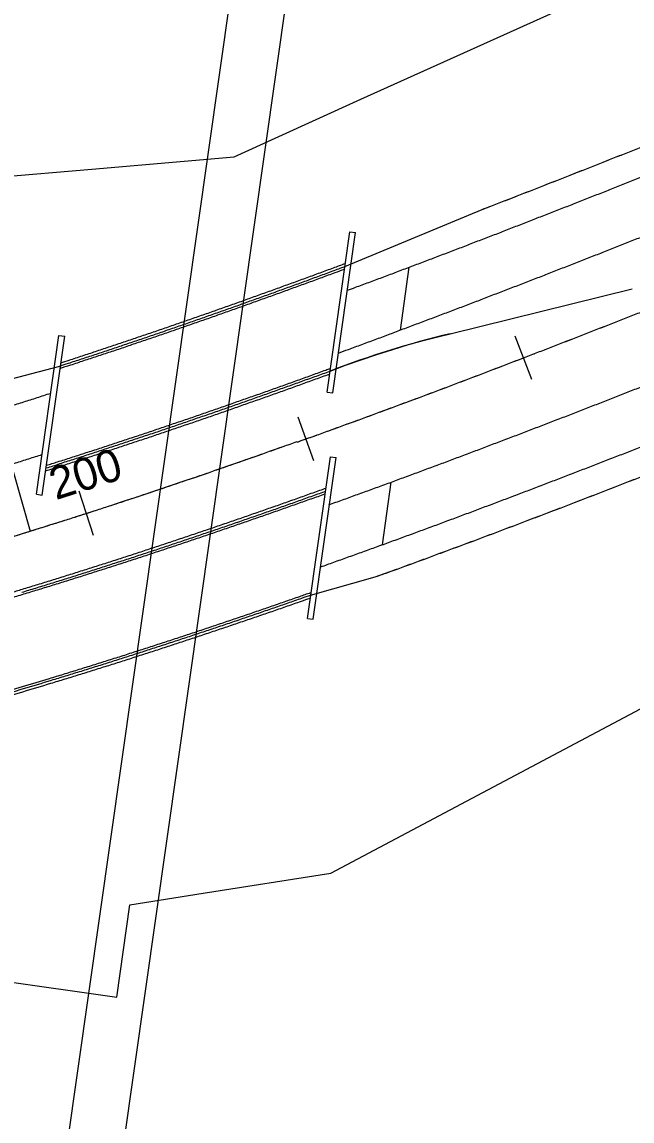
# Model space of a CAD drawing. Extents: x 0 to 3400, y 0 to 2200.
# Drawn here: x 2021.7 to 2284.4, y 258 to 731 of the extents above; entities that cross this region are included whole.
import ezdxf

# ---------------------------------------------------------------- set-up
doc = ezdxf.new("R2010")
doc.units = 0
for name, color, linetype in [('Default', 7, 'Continuous'), ('GE_P_CL_100', 7, 'Continuous'), ('PV_P_EOP', 7, 'Continuous'), ('PV_X_EOP', 7, 'Continuous'), ('RD_X_GR_Lt', 7, 'Continuous'), ('RD_X_GR_Rt', 7, 'Continuous'), ('RW_X_Esmt_LA', 7, 'Continuous'), ('SC_Scratch10', 7, 'Continuous'), ('SH_Data', 7, 'Continuous')]:
    doc.layers.add(name, color=color, linetype=linetype)

msp = doc.modelspace()

# ---------------------------------------------------------------- linework, layer by layer
at = {"layer": 'Default'}
for p, q in [((2160.68, 625.76), (2219.83, 650.31)), ((2160.68, 625.76), (2219.83, 650.31)), ((2153.09, 571.76), (2162.92, 640.75)), ((2155.56, 571.41), (2165.39, 640.4)), ((2162.92, 640.75), (2165.39, 640.4)), ((2184.67, 598.42), (2188.52, 625.5)), ((2206.08, 596.85), (2284.41, 616.22)), ((2206.08, 596.85), (2284.41, 616.22)), ((2027.91, 527.76), (2037.65, 596.09)), ((2037.65, 596.09), (2040.12, 595.74)), ((2030.39, 527.41), (2040.12, 595.74)), ((2241.28, 577.13), (2234.1, 595.79)), ((2153.09, 571.76), (2155.56, 571.41)), ((2147.35, 542.14), (2140.6, 560.97)), ((2144.61, 474.3), (2154.52, 543.85)), ((2147.08, 473.94), (2156.99, 543.5)), ((2154.52, 543.85), (2156.99, 543.5)), ((2176.91, 506.02), (2180.75, 532.97)), ((2027.91, 527.76), (2030.39, 527.41)), ((2052.51, 510), (2046.37, 529.03)), ((2146, 484.38), (2173.87, 492.17)), ((2146, 484.38), (2173.87, 492.17)), ((2144.61, 474.3), (2147.08, 473.94))]:
    msp.add_line(p, q, dxfattribs=at)
for points in [[(2247.02, 590.06), (2247.49, 590.24), (2250.36, 591.35), (2253.23, 592.46), (2256.09, 593.58), (2258.96, 594.69), (2261.83, 595.81), (2264.69, 596.93), (2267.56, 598.05), (2270.42, 599.17), (2273.29, 600.29), (2276.16, 601.41), (2279.02, 602.54), (2281.88, 603.66), (2284.75, 604.79)], [(2237.69, 586.46), (2238.87, 586.91), (2241.74, 588.02), (2242.36, 588.26)], [(2153.39, 554.94), (2155.3, 555.63), (2158.2, 556.68), (2161.09, 557.73), (2163.98, 558.79), (2166.87, 559.84), (2169.76, 560.9), (2172.65, 561.96), (2175.54, 563.02), (2178.42, 564.09), (2181.31, 565.16), (2184.19, 566.23), (2187.08, 567.3), (2189.96, 568.37), (2192.84, 569.45), (2195.73, 570.53), (2198.61, 571.6), (2201.49, 572.69), (2204.37, 573.77), (2207.25, 574.85), (2210.13, 575.94), (2213, 577.03), (2215.88, 578.12), (2218.76, 579.21), (2221.63, 580.31), (2224.51, 581.41), (2227.38, 582.51), (2228.35, 582.88)], [(2233.02, 584.67), (2233.13, 584.71), (2236, 585.81), (2237.69, 586.46)], [(2139.36, 550.15), (2140.05, 550.4), (2140.08, 550.41), (2140.1, 550.42), (2140.24, 550.22), (2141.98, 550.84), (2143.72, 551.46), (2143.98, 551.55)], [(2143.98, 551.55), (2146.62, 552.5), (2148.68, 553.24)], [(2058.95, 522.6), (2060.82, 523.21), (2063.77, 524.17), (2066.72, 525.14), (2069.67, 526.12), (2072.62, 527.1), (2075.56, 528.08), (2078.51, 529.06), (2081.45, 530.05), (2084.39, 531.04), (2087.34, 532.03), (2090.28, 533.03), (2093.22, 534.03), (2096.15, 535.03), (2099.09, 536.03), (2102.02, 537.04), (2104.95, 538.05), (2107.89, 539.07), (2110.82, 540.08), (2113.75, 541.1), (2116.67, 542.13), (2119.6, 543.15), (2122.53, 544.18), (2125.45, 545.21), (2128.37, 546.24), (2131.3, 547.28), (2134.22, 548.32), (2134.65, 548.47)], [(2049.44, 519.51), (2051.96, 520.33), (2054.2, 521.05)], [(1963.23, 493.66), (1979.89, 498.3), (2004.37, 505.47), (2010.43, 507.31), (2013.41, 508.21), (2016.38, 509.12), (2019.35, 510.03), (2022.32, 510.95), (2025.29, 511.87), (2028.26, 512.8), (2031.23, 513.72), (2034.19, 514.66), (2037.16, 515.59), (2039.91, 516.47)], [(2044.68, 517.98), (2046.04, 518.42), (2049, 519.37), (2049.44, 519.51)]]:
    msp.add_lwpolyline(points, dxfattribs=at)
for centre, radius, start, end in [((2301.32, 199.25), 408.84, 103.4712, 111.0638), ((2301.32, 199.25), 408.84, 103.4712, 111.0638), ((1349.37, 2701.71), 2316.83, 286.73456, 286.891), ((1349.37, 2701.71), 2314.66, 286.75999, 286.891), ((1349.37, 2701.71), 2357, 286.27879, 286.891), ((1349.95, 2701.92), 2355.83, 286.27879, 286.891), ((1349.37, 2701.71), 2354.83, 286.3024, 286.891)]:
    msp.add_arc(centre, radius, start, end, dxfattribs=at)
for points in [[(2219.83, 650.31), (2223.67, 651.79), (2229.34, 653.99), (2235.02, 656.2), (2240.7, 658.41), (2246.38, 660.63), (2252.06, 662.85), (2257.73, 665.08), (2263.41, 667.32), (2269.09, 669.56), (2274.78, 671.81), (2280.46, 674.06), (2286.14, 676.31), (2291.82, 678.57), (2297.51, 680.83), (2303.2, 683.1), (2306.07, 684.25)], [(2219.83, 650.31), (2223.67, 651.79), (2229.34, 653.99), (2235.02, 656.2), (2240.7, 658.41), (2246.38, 660.63), (2252.06, 662.85), (2257.73, 665.08), (2263.41, 667.32), (2269.09, 669.56), (2274.78, 671.81), (2280.46, 674.06), (2286.14, 676.31), (2291.82, 678.57), (2297.51, 680.83), (2303.2, 683.1), (2306.07, 684.25)], [(2140.24, 550.22), (2143.72, 551.46), (2149.52, 553.54), (2155.3, 555.63), (2161.09, 557.73), (2166.87, 559.84), (2172.65, 561.96), (2178.42, 564.09), (2184.19, 566.23), (2189.96, 568.37), (2195.73, 570.53), (2201.49, 572.69), (2207.25, 574.85), (2213, 577.03), (2218.76, 579.21), (2224.51, 581.41), (2230.26, 583.61), (2236, 585.81), (2241.74, 588.02), (2247.49, 590.24), (2253.23, 592.46), (2258.96, 594.69), (2264.69, 596.93), (2270.42, 599.17), (2276.16, 601.41), (2281.88, 603.66), (2287.61, 605.91), (2293.33, 608.17), (2299.06, 610.43), (2304.78, 612.7), (2310.5, 614.97), (2316.22, 617.24), (2321.93, 619.52), (2327.65, 621.8), (2333.36, 624.08), (2339.08, 626.36), (2344.79, 628.65), (2350.51, 630.94), (2356.22, 633.23), (2361.93, 635.52), (2367.64, 637.81), (2373.36, 640.1), (2379.07, 642.4), (2384.77, 644.69), (2390.49, 646.99)], [(2038.01, 581.92), (2042.71, 583.44), (2048.42, 585.31), (2054.13, 587.19), (2059.83, 589.08), (2065.53, 590.99), (2071.24, 592.92), (2076.93, 594.85), (2082.63, 596.8), (2088.33, 598.76), (2094.03, 600.73), (2099.72, 602.72), (2105.42, 604.72), (2111.11, 606.72), (2116.79, 608.74), (2122.48, 610.78), (2128.17, 612.82), (2133.86, 614.87), (2139.54, 616.94), (2145.23, 619.01), (2150.92, 621.1), (2156.6, 623.19), (2160.54, 624.65)], [(2038.07, 582.95), (2041.69, 584.13), (2047.4, 585.99), (2053.1, 587.87), (2058.81, 589.77), (2064.51, 591.68), (2070.21, 593.6), (2075.9, 595.53), (2081.6, 597.48), (2087.3, 599.44), (2092.99, 601.41), (2098.68, 603.4), (2104.38, 605.39), (2110.06, 607.4), (2115.75, 609.42), (2121.44, 611.45), (2127.13, 613.49), (2132.81, 615.55), (2138.5, 617.61), (2144.18, 619.68), (2149.86, 621.77), (2155.54, 623.86), (2160.68, 625.76)], [(2038.42, 584.33), (2042.04, 585.5), (2047.74, 587.37), (2053.45, 589.25), (2059.15, 591.14), (2064.84, 593.05), (2070.54, 594.97), (2076.23, 596.9), (2081.93, 598.85), (2087.62, 600.81), (2093.32, 602.78), (2099.01, 604.77), (2104.7, 606.76), (2110.38, 608.77), (2116.07, 610.78), (2121.75, 612.82), (2127.44, 614.86), (2133.12, 616.91), (2138.8, 618.97), (2144.49, 621.05), (2150.17, 623.13), (2155.85, 625.22), (2160.99, 627.12)], [(2032.19, 540.17), (2037.08, 541.71), (2042.88, 543.56), (2048.68, 545.43), (2054.48, 547.31), (2060.27, 549.21), (2066.06, 551.11), (2071.85, 553.04), (2077.63, 554.97), (2083.41, 556.92), (2089.19, 558.88), (2094.96, 560.86), (2100.73, 562.84), (2106.5, 564.84), (2112.27, 566.85), (2118.03, 568.87), (2123.79, 570.9), (2129.54, 572.95), (2135.3, 575), (2141.05, 577.07), (2146.8, 579.14), (2152.54, 581.23), (2154.5, 581.94)], [(2173.87, 492.17), (2177.77, 493.57), (2183.66, 495.71), (2189.54, 497.86), (2195.42, 500.01), (2201.29, 502.18), (2207.15, 504.35), (2213.01, 506.53), (2218.86, 508.71), (2224.71, 510.91), (2230.55, 513.11), (2236.39, 515.31), (2242.22, 517.53), (2248.05, 519.75), (2253.87, 521.97), (2259.68, 524.21), (2265.49, 526.44), (2271.3, 528.69), (2277.1, 530.93), (2282.9, 533.19), (2288.68, 535.44), (2294.47, 537.7), (2300.25, 539.97), (2306.03, 542.24), (2311.81, 544.51), (2317.57, 546.79), (2323.34, 549.06), (2329.1, 551.35), (2334.86, 553.63), (2340.61, 555.92), (2346.36, 558.2), (2352.11, 560.5), (2357.85, 562.79), (2363.58, 565.08), (2369.32, 567.38), (2375.05, 569.67), (2380.78, 571.97), (2386.51, 574.26), (2392.23, 576.56), (2397.95, 578.86), (2403.67, 581.15), (2409.38, 583.45), (2415.09, 585.74)], [(2173.87, 492.17), (2177.77, 493.57), (2183.66, 495.71), (2189.54, 497.86), (2195.42, 500.01), (2201.29, 502.18), (2207.15, 504.35), (2213.01, 506.53), (2218.86, 508.71), (2224.71, 510.91), (2230.55, 513.11), (2236.39, 515.31), (2242.22, 517.53), (2248.05, 519.75), (2253.87, 521.97), (2259.68, 524.21), (2265.49, 526.44), (2271.3, 528.69), (2277.1, 530.93), (2282.9, 533.19), (2288.68, 535.44), (2294.47, 537.7), (2300.25, 539.97), (2306.03, 542.24), (2311.81, 544.51), (2317.57, 546.79), (2323.34, 549.06), (2329.1, 551.35), (2334.86, 553.63), (2340.61, 555.92), (2346.36, 558.2), (2352.11, 560.5), (2357.85, 562.79), (2363.58, 565.08), (2369.32, 567.38), (2375.05, 569.67), (2380.78, 571.97), (2386.51, 574.26), (2392.23, 576.56), (2397.95, 578.86), (2403.67, 581.15), (2409.38, 583.45), (2415.09, 585.74)], [(2031.89, 537.8), (2031.92, 537.81), (2037.73, 539.65), (2043.54, 541.5), (2049.35, 543.37), (2055.15, 545.25), (2060.95, 547.15), (2066.74, 549.06), (2072.54, 550.98), (2078.32, 552.92), (2084.11, 554.87), (2089.89, 556.83), (2095.67, 558.81), (2101.44, 560.79), (2107.21, 562.79), (2112.98, 564.8), (2118.75, 566.83), (2124.51, 568.86), (2130.27, 570.91), (2136.02, 572.96), (2141.78, 575.03), (2147.53, 577.11), (2153.28, 579.19), (2154.15, 579.51)], [(2032.16, 539.08), (2032.2, 539.09), (2038.01, 540.93), (2043.81, 542.78), (2049.61, 544.65), (2055.42, 546.53), (2061.21, 548.43), (2067, 550.34), (2072.79, 552.26), (2078.58, 554.2), (2084.36, 556.14), (2090.14, 558.11), (2095.91, 560.08), (2101.69, 562.07), (2107.46, 564.07), (2113.22, 566.08), (2118.99, 568.1), (2124.75, 570.13), (2130.5, 572.18), (2136.26, 574.23), (2142.01, 576.3), (2147.76, 578.37), (2153.51, 580.46), (2154.38, 580.78)], [(2010.43, 507.31), (2016.38, 509.12), (2022.32, 510.95), (2028.26, 512.8), (2034.19, 514.66), (2040.12, 516.53), (2046.04, 518.42), (2051.96, 520.33), (2057.87, 522.24), (2063.77, 524.17), (2069.67, 526.12), (2075.56, 528.08), (2081.45, 530.05), (2087.34, 532.03), (2093.22, 534.03), (2099.09, 536.03), (2104.95, 538.05), (2110.82, 540.08), (2116.67, 542.13), (2122.53, 544.18), (2128.37, 546.24), (2134.22, 548.32), (2140.05, 550.4), (2140.1, 550.42)], [(2021.9, 486.9), (2027.84, 488.72), (2033.78, 490.55), (2039.71, 492.39), (2045.64, 494.25), (2051.56, 496.12), (2057.48, 498.01), (2063.39, 499.91), (2069.29, 501.83), (2075.19, 503.76), (2081.09, 505.7), (2086.98, 507.66), (2092.86, 509.63), (2098.74, 511.61), (2104.61, 513.6), (2110.48, 515.61), (2116.35, 517.63), (2122.2, 519.66), (2128.06, 521.7), (2133.91, 523.75), (2139.75, 525.81), (2145.59, 527.89), (2151.42, 529.97), (2152.54, 530.37)], [(2021.72, 485.57), (2027.67, 487.39), (2033.61, 489.22), (2039.55, 491.06), (2045.48, 492.92), (2051.4, 494.8), (2057.32, 496.69), (2063.23, 498.59), (2069.14, 500.5), (2075.04, 502.43), (2080.94, 504.38), (2086.83, 506.34), (2092.72, 508.31), (2098.6, 510.29), (2104.47, 512.28), (2110.34, 514.29), (2116.21, 516.31), (2122.07, 518.34), (2127.92, 520.38), (2133.78, 522.43), (2139.62, 524.5), (2145.46, 526.57), (2151.3, 528.65), (2152.41, 529.05)], [(2022.53, 484.83), (2028.48, 486.65), (2034.42, 488.48), (2040.36, 490.32), (2046.29, 492.18), (2052.22, 494.06), (2058.14, 495.95), (2064.06, 497.85), (2069.97, 499.77), (2075.87, 501.7), (2081.77, 503.65), (2087.66, 505.6), (2093.55, 507.57), (2099.43, 509.56), (2105.31, 511.55), (2111.19, 513.56), (2117.05, 515.58), (2122.92, 517.61), (2128.77, 519.65), (2134.62, 521.7), (2140.47, 523.77), (2146.32, 525.84), (2152.15, 527.93), (2152.2, 527.95)], [(2033.57, 448.47), (2039.61, 450.32), (2045.65, 452.17), (2051.69, 454.05), (2057.71, 455.94), (2063.73, 457.84), (2069.74, 459.76), (2075.74, 461.69), (2081.74, 463.64), (2087.73, 465.6), (2093.71, 467.57), (2099.68, 469.55), (2105.65, 471.55), (2111.61, 473.56), (2117.57, 475.58), (2123.51, 477.61), (2129.46, 479.66), (2135.39, 481.72), (2141.32, 483.78), (2146.06, 485.45)], [(2034.2, 446.4), (2040.25, 448.24), (2046.29, 450.1), (2052.33, 451.98), (2058.36, 453.87), (2064.39, 455.78), (2070.4, 457.7), (2076.41, 459.63), (2082.41, 461.58), (2088.4, 463.54), (2094.39, 465.51), (2100.37, 467.5), (2106.34, 469.5), (2112.31, 471.51), (2118.26, 473.53), (2124.21, 475.56), (2130.16, 477.61), (2136.1, 479.67), (2142.03, 481.74), (2145.81, 483.06)], [(2034.44, 447.73), (2040.49, 449.57), (2046.53, 451.43), (2052.56, 453.31), (2058.59, 455.2), (2064.61, 457.1), (2070.63, 459.02), (2076.63, 460.96), (2082.62, 462.9), (2088.62, 464.86), (2094.6, 466.83), (2100.58, 468.82), (2106.55, 470.82), (2112.51, 472.83), (2118.47, 474.85), (2124.42, 476.88), (2130.36, 478.93), (2136.3, 480.99), (2142.23, 483.05), (2146, 484.38)]]:
    msp.add_spline(points, degree=3, dxfattribs=at)
at = {"layer": 'PV_P_EOP'}
for points in [[(2161.94, 615.57), (2165.41, 616.85), (2171.1, 618.97), (2176.8, 621.1), (2182.49, 623.23), (2188.18, 625.38), (2193.87, 627.53), (2199.56, 629.69), (2205.25, 631.85), (2210.94, 634.03), (2216.63, 636.22), (2222.31, 638.4), (2228, 640.6), (2233.68, 642.8), (2239.37, 645.02), (2245.06, 647.23), (2250.75, 649.45), (2256.44, 651.68), (2262.12, 653.92), (2267.81, 656.15), (2273.5, 658.4), (2279.19, 660.65), (2284.88, 662.9), (2290.57, 665.16), (2296.26, 667.42), (2301.95, 669.69), (2307.64, 671.95), (2313.34, 674.23), (2319.03, 676.51), (2324.73, 678.78), (2330.42, 681.06), (2336.13, 683.35), (2341.83, 685.63), (2347.53, 687.92), (2353.23, 690.21), (2358.94, 692.5), (2364.64, 694.8), (2370.35, 697.09)], [(2157.96, 588.53), (2162.3, 590.12), (2168.03, 592.23), (2173.76, 594.35), (2179.48, 596.48), (2185.21, 598.62), (2190.93, 600.77), (2196.66, 602.92), (2202.38, 605.09), (2208.09, 607.26), (2213.81, 609.43), (2219.52, 611.62), (2225.24, 613.81), (2230.95, 616.01), (2236.66, 618.22), (2242.37, 620.43), (2248.08, 622.65), (2253.79, 624.87), (2259.5, 627.1), (2265.2, 629.34), (2270.91, 631.58), (2276.61, 633.82), (2282.32, 636.08), (2288.02, 638.33), (2293.72, 640.59), (2299.42, 642.85), (2305.13, 645.12), (2310.83, 647.39), (2316.54, 649.66), (2322.24, 651.94), (2327.94, 654.22), (2333.65, 656.5), (2339.35, 658.79), (2345.06, 661.07), (2350.76, 663.36), (2356.47, 665.65), (2362.17, 667.94), (2367.88, 670.23), (2373.59, 672.53), (2379.3, 674.82)], [(2153.92, 523.25), (2159.68, 525.32), (2165.51, 527.43), (2171.35, 529.54), (2177.18, 531.67), (2183, 533.8), (2188.82, 535.95), (2194.63, 538.1), (2200.44, 540.26), (2206.24, 542.43), (2212.05, 544.6), (2217.84, 546.79), (2223.63, 548.98), (2229.42, 551.17), (2235.21, 553.38), (2240.99, 555.59), (2246.76, 557.81), (2252.54, 560.03), (2258.31, 562.26), (2264.08, 564.5), (2269.84, 566.73), (2275.6, 568.98), (2281.35, 571.23), (2287.11, 573.48), (2292.86, 575.74), (2298.61, 578), (2304.35, 580.27), (2310.09, 582.54), (2315.83, 584.81), (2321.57, 587.09), (2327.3, 589.37), (2333.04, 591.65), (2338.77, 593.93), (2344.49, 596.22), (2350.22, 598.51), (2355.94, 600.8), (2361.67, 603.09), (2367.38, 605.38), (2373.1, 607.67), (2378.82, 609.97), (2384.53, 612.26), (2390.25, 614.56), (2395.96, 616.85), (2401.67, 619.15)], [(2150.37, 496.51), (2156.04, 498.52), (2161.93, 500.63), (2167.81, 502.74), (2173.68, 504.86), (2179.56, 506.99), (2185.42, 509.13), (2191.28, 511.28), (2197.13, 513.43), (2202.98, 515.6), (2208.82, 517.77), (2214.66, 519.95), (2220.49, 522.14), (2226.32, 524.33), (2232.13, 526.53), (2237.95, 528.74), (2243.77, 530.96), (2249.58, 533.18), (2255.38, 535.41), (2261.18, 537.64), (2266.97, 539.88), (2272.76, 542.12), (2278.54, 544.37), (2284.32, 546.62), (2290.1, 548.88), (2295.87, 551.14), (2301.64, 553.4), (2307.41, 555.68), (2313.17, 557.95), (2318.92, 560.22), (2324.68, 562.5), (2330.43, 564.78), (2336.18, 567.07), (2341.92, 569.35), (2347.66, 571.64), (2353.4, 573.93), (2359.13, 576.22), (2364.86, 578.52), (2370.59, 580.81), (2376.32, 583.1), (2382.04, 585.4), (2387.76, 587.7), (2393.47, 589.99), (2399.19, 592.29), (2404.91, 594.58), (2410.62, 596.88)], [(1999.57, 560.42), (2005.32, 562.18), (2011.07, 563.95), (2016.81, 565.73), (2022.55, 567.53), (2028.29, 569.35), (2034.03, 571.18), (2034.11, 571.2)], [(2006.55, 537.46), (2012.36, 539.23), (2018.16, 541.02), (2023.97, 542.82), (2029.77, 544.64), (2030.19, 544.77)]]:
    msp.add_spline(points, degree=3, dxfattribs=at)
at = {"layer": 'PV_X_EOP'}
for p, q in [((2028.55, 158.97), (2119.6, 798.08)), ((2052.31, 155.58), (2143.36, 794.69))]:
    msp.add_line(p, q, dxfattribs=at)
at = {"layer": 'RD_X_GR_Lt'}
msp.add_line((1996.09, 571.91), (2038.07, 582.95), dxfattribs=at)
msp.add_lwpolyline([(2160.68, 625.76), (2219.83, 650.31), (2221.75, 651.05), (2223.67, 651.79), (2226.51, 652.89), (2229.34, 653.99), (2232.18, 655.09), (2235.02, 656.2), (2237.86, 657.3), (2240.7, 658.41), (2243.54, 659.52), (2246.38, 660.63), (2249.22, 661.74), (2252.06, 662.85), (2254.89, 663.97), (2257.73, 665.08), (2260.57, 666.2), (2263.41, 667.32), (2266.25, 668.44), (2269.09, 669.56), (2271.93, 670.68), (2274.78, 671.81), (2277.62, 672.93), (2280.46, 674.06), (2283.3, 675.18), (2286.14, 676.31)], dxfattribs=at)
at = {"layer": 'RD_X_GR_Rt'}
for points in [[(2154.38, 580.78), (2161.07, 583.31), (2167.78, 585.68), (2174.54, 587.93), (2181.36, 590.12), (2188.21, 592.14), (2195.06, 594.03), (2201.97, 595.86), (2206.08, 596.85), (2284.41, 616.22)], [(2146, 484.38), (2173.87, 492.17), (2175.82, 492.87), (2177.77, 493.57), (2180.71, 494.64), (2183.66, 495.71), (2186.6, 496.79), (2189.54, 497.86), (2192.48, 498.94), (2195.42, 500.01), (2198.35, 501.09), (2201.29, 502.18), (2204.22, 503.26), (2207.15, 504.35), (2210.08, 505.44), (2213.01, 506.53), (2215.94, 507.62), (2218.86, 508.71), (2221.79, 509.81), (2224.71, 510.91), (2227.63, 512.01), (2230.55, 513.11), (2233.47, 514.21), (2236.39, 515.31), (2239.3, 516.42), (2242.22, 517.53), (2245.14, 518.64), (2248.05, 519.75), (2250.96, 520.86), (2253.87, 521.97), (2256.78, 523.09), (2259.68, 524.21), (2262.59, 525.32), (2265.49, 526.44), (2268.4, 527.56), (2271.3, 528.69), (2274.2, 529.81), (2277.1, 530.93), (2280, 532.06), (2282.9, 533.19), (2285.79, 534.31)]]:
    msp.add_lwpolyline(points, dxfattribs=at)
at = {"layer": 'RW_X_Esmt_LA'}
for p, q in [((2167.64, 697.84), (2440.04, 820.55)), ((2113.05, 673.03), (2167.64, 697.84)), ((2051.81, 667.67), (2113.05, 673.03)), ((1405.26, 614.11), (2051.81, 667.67)), ((2154.68, 364.62), (2357.68, 472.31)), ((2099.74, 355.98), (2154.68, 364.62)), ((2068.12, 351), (2099.74, 355.98)), ((2062.52, 311.23), (2068.12, 351)), ((1930.33, 330), (2062.52, 311.23))]:
    msp.add_line(p, q, dxfattribs=at)
at = {"layer": 'SC_Scratch10'}
for p, q in [((2237.69, 586.46), (2237.69, 586.46)), ((2143.98, 551.55), (2143.98, 551.55)), ((2049.44, 519.51), (2049.44, 519.51))]:
    msp.add_line(p, q, dxfattribs=at)
at = {"layer": 'SH_Data'}
msp.add_line((1917.37, 889.49), (2025.25, 511.86), dxfattribs=at)

# ---------------------------------------------------------------- texts
at = {"layer": 'GE_P_CL_100'}
msp.add_text('200', height=14, rotation=17.741, dxfattribs=at).set_placement((2036.28, 525.17))

doc.saveas('drawing.dxf')
